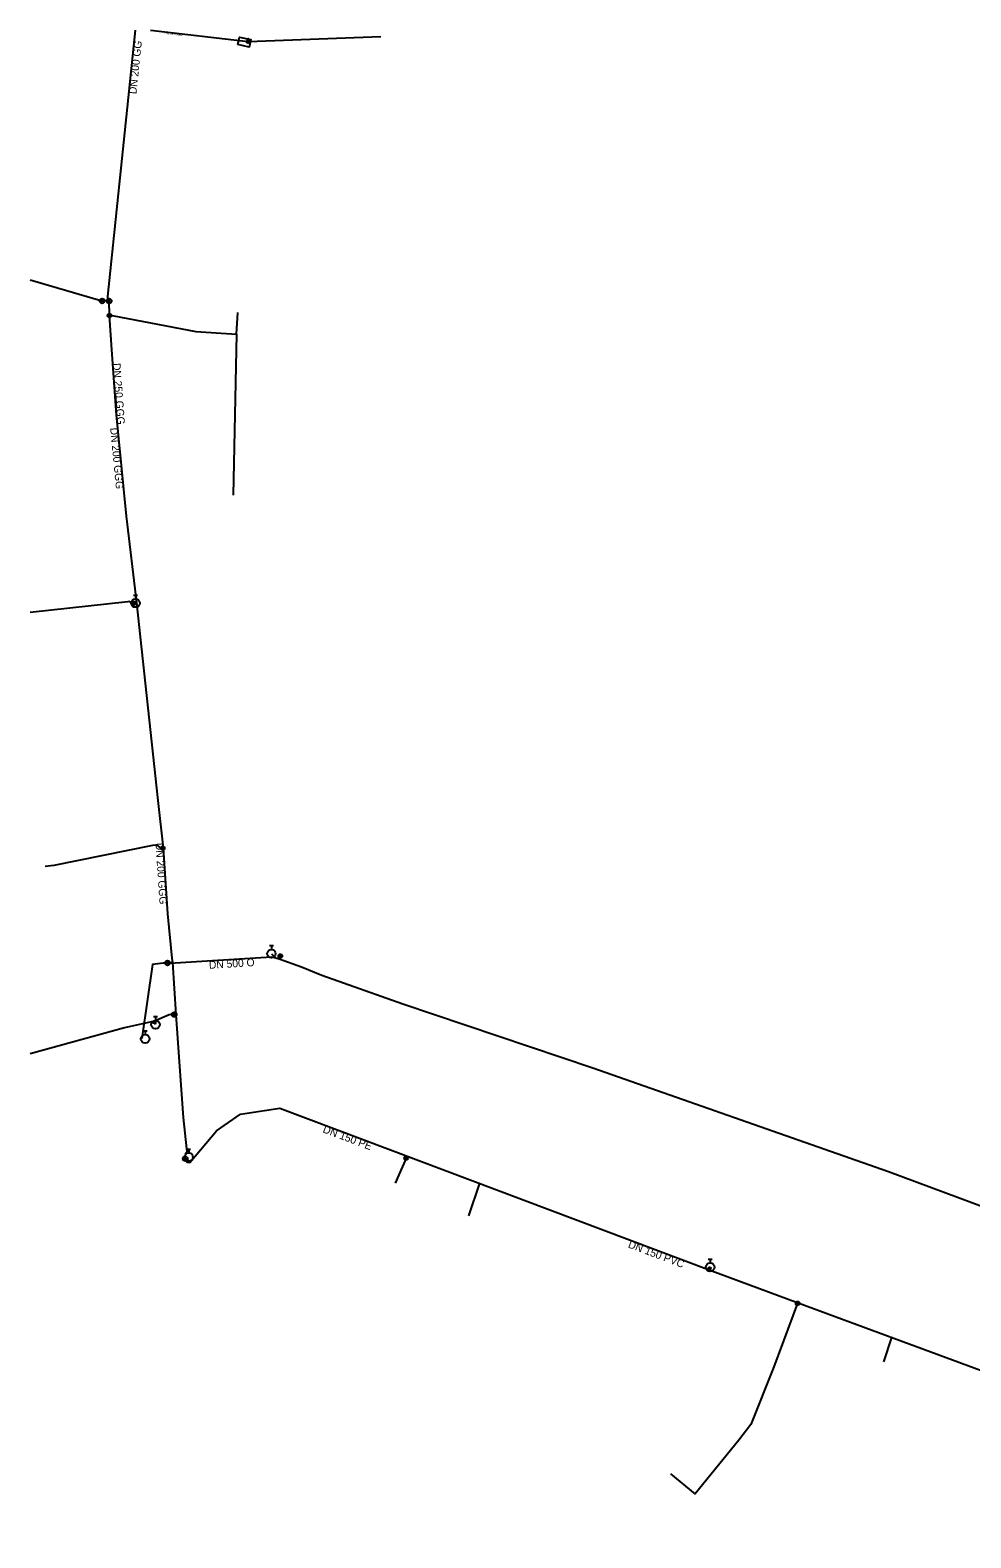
# Model space of a CAD drawing. Extents: x -464617 to -463917, y -1094288 to -1093929.
# Drawn here: x -464616.5 to -464420.1, y -1094244.3 to -1093929.4 of the extents above; entities that cross this region are included whole.
import ezdxf

# ---------------------------------------------------------------- set-up
doc = ezdxf.new("R2010")
doc.units = 0
for name, color, linetype in [('_hydrantova_odbocka_', 7, 'Continuous'), ('_pripojka_prevzato_z_dokumentace_', 7, 'Continuous'), ('_pripojka_priblizne_', 7, 'Continuous'), ('_sachta_voda_', 7, 'Continuous'), ('_voda_smvak_prevzato_z_dokumentace_', 7, 'Continuous'), ('_voda_smvak_priblizne_', 7, 'Continuous'), ('_vodovodni_chranicka_', 7, 'Continuous'), ('Default', 7, 'Continuous'), ('MoLevel 2', 7, 'Continuous'), ('MoLevel 27', 7, 'Continuous'), ('MoLevel 28', 7, 'Continuous'), ('MoLevel 30', 7, 'Continuous'), ('MoLevel 42', 7, 'Continuous'), ('MoLevel 46', 7, 'Continuous'), ('MoLevel 53', 7, 'Continuous'), ('MoLevel 55', 7, 'Continuous'), ('MoLevel 60', 7, 'Continuous')]:
    doc.layers.add(name, color=color, linetype=linetype)

# ---------------------------------------------------------------- blocks, each defined once
blk = doc.blocks.new('_uzaver_')
at = {"layer": 'Default'}
for p, q in [((-0.000035, -0.000035), (0.000035, 0.000035)), ((0.000035, -0.000035), (-0.000035, 0.000035))]:
    blk.add_line(p, q, dxfattribs=at)
for radius in [0.00005, 0.0000025]:
    blk.add_circle((0, 0), radius, dxfattribs=at)
blk = doc.blocks.new('_uzaver_pripojka_')
at = {"layer": 'Default'}
for p, q in [((-0.000035, -0.000035), (0.000035, 0.000035)), ((0.000035, -0.000035), (-0.000035, 0.000035))]:
    blk.add_line(p, q, dxfattribs=at)
for radius in [0.00005, 0.0000025]:
    blk.add_circle((0, 0), radius, dxfattribs=at)
blk = doc.blocks.new('_hydrant_voda_')
at = {"layer": 'Default'}
for p, q in [((-0.000023, 0.000095), (0.000023, 0.000095)), ((0, 0.000095), (0, 0.00005))]:
    blk.add_line(p, q, dxfattribs=at)
blk.add_circle((0, 0), 0.00005, dxfattribs=at)
blk = doc.blocks.new('_sachta_voda_')
at = {"layer": 'Default'}
blk.add_line((0, 0.000035), (0, 0.00005), dxfattribs=at)
blk.add_lwpolyline([(-0.000015, 0.00005), (0, 0.000065), (0.000015, 0.00005), (0.000003, 0.00005)], close=True, dxfattribs=at)
blk.add_circle((0, 0), 0.000035, dxfattribs=at)
blk = doc.blocks.new('_poklop_voda_')
at = {"layer": 'Default'}
blk.add_lwpolyline([(-0.00002, 0.00002), (0.00002, 0.00002), (0.00002, -0.00002), (-0.00002, -0.00002), (-0.00002, 0.00002)], dxfattribs=at)

msp = doc.modelspace()

# ---------------------------------------------------------------- linework, layer by layer
at = {"layer": '_hydrantova_odbocka_'}
for points in [[(-464566.14, -1094122.32), (-464565.39, -1094123.06), (-464565.5, -1094123.21)], [(-464590.34, -1094137.14), (-464590.55, -1094136.63), (-464590.56, -1094136.45)], [(-464474.73, -1094188.39), (-464474.63, -1094188.07), (-464474.53, -1094187.79)]]:
    msp.add_lwpolyline(points, dxfattribs=at)
at = {"layer": '_pripojka_prevzato_z_dokumentace_'}
for p, q in [((-464591.41, -1093929.4), (-464570.97, -1093931.8)), ((-464599.95, -1093989.03), (-464599.38, -1093989.02))]:
    msp.add_line(p, q, dxfattribs=at)
for points in [[(-464594.22, -1094049.06), (-464594.85, -1094049.12), (-464595.14, -1094049.15), (-464595.75, -1094048.76), (-464596.15, -1094048.79)], [(-464588.67, -1094100.25), (-464588.83, -1094100.27), (-464589.16, -1094100.29), (-464589.99, -1094099.67), (-464590.94, -1094099.72)]]:
    msp.add_lwpolyline(points, dxfattribs=at)
at = {"layer": '_pripojka_priblizne_'}
for p, q in [((-464570.97, -1093931.8), (-464543.26, -1093930.71)), ((-464573.44, -1093992.89), (-464573.13, -1093988.41)), ((-464596.15, -1094048.79), (-464616.51, -1094051.02)), ((-464564.29, -1094122.82), (-464564.5, -1094123.44)), ((-464522.72, -1094170.27), (-464525, -1094177.06)), ((-464438.27, -1094207.58), (-464436.59, -1094202.48))]:
    msp.add_line(p, q, dxfattribs=at)
for points in [[(-464599.38, -1093989.02), (-464581.94, -1093992.37), (-464573.44, -1093992.89), (-464574.1, -1094026.55)], [(-464590.94, -1094099.72), (-464611.58, -1094103.92), (-464613.36, -1094104.12)], [(-464537.86, -1094164.57), (-464538.01, -1094165.02), (-464540.27, -1094170.29)], [(-464456.17, -1094195.24), (-464456.26, -1094195.36), (-464461.24, -1094208.61), (-464466, -1094220.66), (-464468.54, -1094223.97), (-464477.65, -1094235.17), (-464482.71, -1094231)]]:
    msp.add_lwpolyline(points, dxfattribs=at)
at = {"layer": '_sachta_voda_'}
msp.add_lwpolyline([(-464573.15, -1093932.41), (-464572.8, -1093930.9), (-464570.45, -1093931.36), (-464570.75, -1093932.97)], close=True, dxfattribs=at)
at = {"layer": '_voda_smvak_prevzato_z_dokumentace_'}
for p, q in [((-464600.31, -1093985.01), (-464594.51, -1093929.4)), ((-464601.75, -1093985.97), (-464616.51, -1093981.64)), ((-464601.49, -1093985.97), (-464601.75, -1093985.97)), ((-464600.3, -1093985.52), (-464600.31, -1093985.01)), ((-464587.84, -1094124.26), (-464588.71, -1094124.31)), ((-464586.04, -1094135.02), (-464586.75, -1094124.19)), ((-464587.48, -1094135.08), (-464590.56, -1094136.45)), ((-464586.44, -1094135.04), (-464587.48, -1094135.08)), ((-464586.04, -1094135.02), (-464586.44, -1094135.04)), ((-464529.98, -1094167.54), (-464474.73, -1094188.39))]:
    msp.add_line(p, q, dxfattribs=at)
for points in [[(-464600.3, -1093985.52), (-464600.29, -1093985.96), (-464601.49, -1093985.97)], [(-464600, -1093985.99), (-464600.01, -1093985.51), (-464600.3, -1093985.52)], [(-464594.22, -1094049.06), (-464596.42, -1094030.93), (-464598.47, -1094009.76), (-464599.39, -1093997.15), (-464599.95, -1093989.03), (-464600, -1093985.99)], [(-464586.75, -1094124.19), (-464586.84, -1094123.29), (-464587.74, -1094114.03), (-464588.67, -1094100.25), (-464589.82, -1094090.3), (-464594.22, -1094049.06)], [(-464586.75, -1094124.19), (-464587.04, -1094124.21), (-464587.23, -1094124.21), (-464587.84, -1094124.26)], [(-463938.35, -1094193.12), (-464075.49, -1094227.95), (-464134.41, -1094223.46), (-464163.79, -1094214.62), (-464202, -1094202.35), (-464255.09, -1094244.35), (-464271.29, -1094237.84), (-464272.2, -1094237.58), (-464367.49, -1094207.05), (-464368.8, -1094203.51), (-464371.89, -1094195.64), (-464375, -1094191.05), (-464437.3, -1094167.91), (-464498.99, -1094146.23), (-464538.72, -1094132.85), (-464555.61, -1094126.9), (-464559.83, -1094125.15), (-464564.5, -1094123.44), (-464565.5, -1094123.21)], [(-464590.56, -1094136.45), (-464596.85, -1094137.81), (-464616.51, -1094143.25)], [(-464584.17, -1094164.2), (-464583.71, -1094163.6), (-464583.77, -1094163.07), (-464584.51, -1094156.57), (-464585.34, -1094144.94), (-464586.04, -1094135.02)], [(-464583.83, -1094165.37), (-464583.78, -1094165.85), (-464583.17, -1094165.91), (-464577.6, -1094159.36), (-464572.59, -1094155.82), (-464571.68, -1094155.68)], [(-464571.68, -1094155.68), (-464564.38, -1094154.56), (-464564.38, -1094154.56), (-464529.98, -1094167.54)], [(-464474.73, -1094188.39), (-464456.17, -1094195.24), (-464380.8, -1094223.12)]]:
    msp.add_lwpolyline(points, dxfattribs=at)
at = {"layer": '_voda_smvak_priblizne_'}
for points in [[(-464588.71, -1094124.31), (-464591, -1094124.55), (-464593.2, -1094140.07)], [(-464565.5, -1094123.21), (-464566.13, -1094123.08), (-464587.38, -1094124.38), (-464588.71, -1094124.31)]]:
    msp.add_lwpolyline(points, dxfattribs=at)
at = {"layer": '_vodovodni_chranicka_'}
msp.add_line((-464598.79, -1094005.39), (-464598.58, -1094008.26), dxfattribs=at)

# ---------------------------------------------------------------- block references
at = {"layer": 'MoLevel 27', "xscale": 10000, "yscale": 10000}
for p in [(-464601.49, -1093985.97), (-464587.84, -1094124.26), (-464586.44, -1094135.04)]:
    msp.add_blockref('_uzaver_', p, dxfattribs=at)
at = {"layer": 'MoLevel 27'}
for p, xscale, yscale, rotation in [((-464600, -1093985.99), 10000, 10000, 91.6659304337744), ((-464590.55, -1094136.63), 5000, 4999.999999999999, -67.23499089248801), ((-464584.12, -1094165.15), 10000, 10000, -43.07272542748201), ((-464474.63, -1094188.07), 5000, 5000.000000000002, 66.8936731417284)]:
    msp.add_blockref('_uzaver_', p, dxfattribs=dict(at, xscale=xscale, yscale=yscale, rotation=rotation))
at = {"layer": 'MoLevel 28', "xscale": 17636.68430335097, "yscale": 17636.68430335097}
for p in [(-464594.53, -1094049.09), (-464566.14, -1094122.32), (-464590.34, -1094137.14), (-464592.51, -1094140.11), (-464583.41, -1094164.81), (-464474.53, -1094187.8)]:
    msp.add_blockref('_hydrant_voda_', p, dxfattribs=at)
at = {"layer": 'MoLevel 30', "xscale": 10000, "yscale": 10000}
msp.add_blockref('_sachta_voda_', (-464570.97, -1093931.8), dxfattribs=at)
at = {"layer": 'MoLevel 42', "xscale": 10000, "yscale": 10000}
msp.add_blockref('_poklop_voda_', (-464570.97, -1093931.8), dxfattribs=at)
at = {"layer": 'MoLevel 53', "xscale": 7999.999999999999, "yscale": 7999.999999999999}
for p in [(-464599.95, -1093989.03), (-464594.85, -1094049.12), (-464588.83, -1094100.27), (-464564.29, -1094122.82), (-464538.01, -1094165.02), (-464456.26, -1094195.36)]:
    msp.add_blockref('_uzaver_pripojka_', p, dxfattribs=at)

# ---------------------------------------------------------------- texts
at = {"layer": 'MoLevel 2'}
msp.add_text('DN 500 O', height=1.605, rotation=3.4896, dxfattribs=at).set_placement((-464579.14, -1094125.49))
at = {"layer": 'MoLevel 46'}
for s, rotation, p in [('DN 200 GG', 84.0468, (-464594.34, -1093942.83)), ('DN 200 GGG', 275.531, (-464599.82, -1094012.51)), ('DN 200 GGG', 273.861, (-464590.35, -1094099.22)), ('DN 150 PE', 339.3282, (-464555.54, -1094159.61)), ('DN 150 PVC', 339.3286, (-464491.79, -1094183.66))]:
    msp.add_text(s, height=1.605, rotation=rotation, dxfattribs=at).set_placement(p)
at = {"layer": 'MoLevel 55'}
msp.add_text('DN 150 GGG', height=0.455, rotation=353.3109, dxfattribs=at).set_placement((-464588.46, -1093930.21))
at = {"layer": 'MoLevel 60'}
msp.add_text('DN 250 GGG', height=1.605, rotation=274.1849, dxfattribs=at).set_placement((-464599.26, -1093999.01))

doc.saveas('drawing.dxf')
